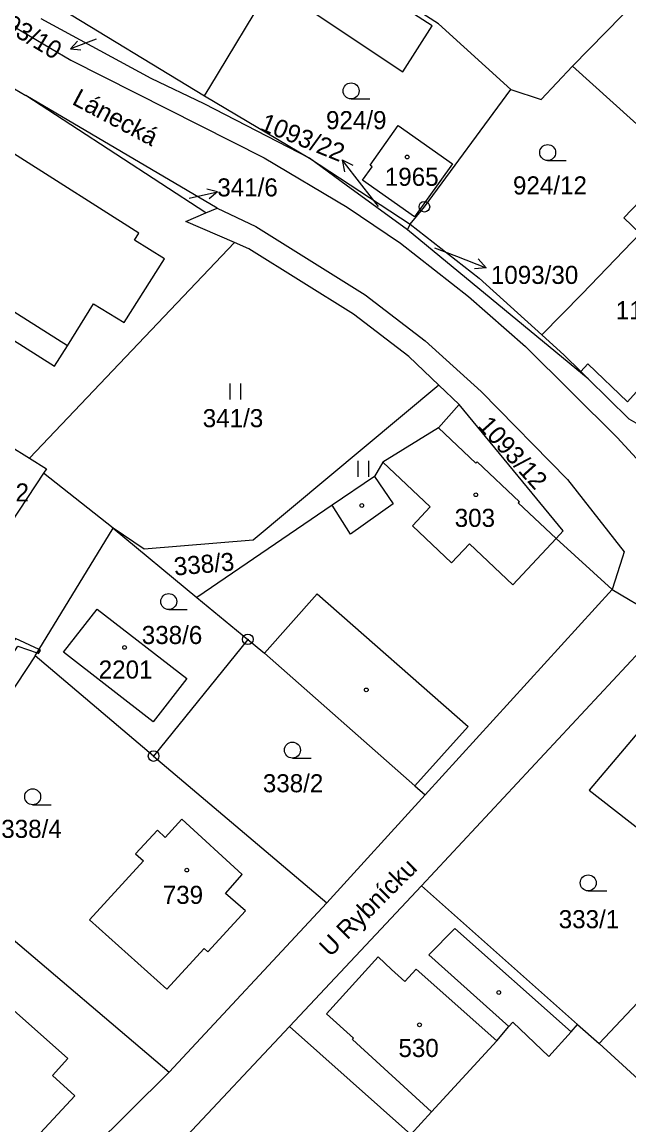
# Model space of a CAD drawing. Extents: x -680203 to -673936, y -1102717 to -1093650.
# Drawn here: x -679269.8 to -679212.8, y -1098015.1 to -1097911.3 of the extents above; entities that cross this region are included whole.
import ezdxf

# ---------------------------------------------------------------- set-up
doc = ezdxf.new("R2010")
doc.units = 0
for name, color, linetype in [('SOxx02xx_Koleje_param další_Popis10', 7, 'Continuous'), ('SOxx02xx_Staničení_Popis10', 7, 'Continuous'), ('SOxxxxxx_Koleje_hlavní_body_Popis10', 7, 'Continuous'), ('SOxxxxxx_Koleje_LN_parametry_Popis10', 7, 'Continuous'), ('SOxxxxxx_Koleje_param další_Popis10', 7, 'Continuous'), ('SOxxxxxx_Osa_bod_P', 7, 'Continuous'), ('SOxxxxxx_Staničení_Popis10', 7, 'Continuous'), ('x_prac', 7, 'Continuous')]:
    doc.layers.add(name, color=color, linetype=linetype)

msp = doc.modelspace()

# ---------------------------------------------------------------- linework, layer by layer
at = {"layer": 'SOxx02xx_Koleje_param další_Popis10'}
for centre, radius in [((-679231.98, -1097928.68), 0.5), ((-679231.98, -1097928.68), 0.0303), ((-679248.58, -1097969.38), 0.5), ((-679248.58, -1097969.38), 0.0303), ((-679257.44, -1097980.36), 0.5), ((-679257.44, -1097980.36), 0.0303)]:
    msp.add_circle(centre, radius, dxfattribs=at)
at = {"layer": 'SOxx02xx_Staničení_Popis10'}
for p, q in [((-679262.83, -1097912.9), (-679265.24, -1097913.82)), ((-679265.24, -1097913.82), (-679264.59, -1097913.11)), ((-679265.24, -1097913.82), (-679264.28, -1097913.92)), ((-679237.86, -1097926.65), (-679239.71, -1097924.28)), ((-679239.71, -1097924.28), (-679238.7, -1097924.77)), ((-679239.71, -1097924.28), (-679239.49, -1097925.38)), ((-679254.1, -1097927.88), (-679251.44, -1097927.27)), ((-679251.44, -1097927.27), (-679252.43, -1097927.03)), ((-679251.44, -1097927.27), (-679252.22, -1097927.92)), ((-679236.28, -1097928.65), (-679237.86, -1097926.65)), ((-679231.03, -1097932.54), (-679228.97, -1097933.34)), ((-679228.97, -1097933.34), (-679226.17, -1097934.42)), ((-679226.17, -1097934.42), (-679226.92, -1097933.59)), ((-679226.17, -1097934.42), (-679227.28, -1097934.52))]:
    msp.add_line(p, q, dxfattribs=at)
at = {"layer": 'SOxxxxxx_Koleje_hlavní_body_Popis10'}
for p, q in [((-679238.87, -1097918.53), (-679237.12, -1097918.53)), ((-679220.39, -1097924.33), (-679218.64, -1097924.33)), ((-679250.24, -1097946.81), (-679250.24, -1097945.31)), ((-679249.24, -1097946.81), (-679249.24, -1097945.31)), ((-679238.21, -1097954.09), (-679238.21, -1097952.59)), ((-679237.21, -1097954.09), (-679237.21, -1097952.59)), ((-679256.02, -1097966.58), (-679254.27, -1097966.58)), ((-679244.39, -1097980.55), (-679242.64, -1097980.55)), ((-679268.81, -1097984.94), (-679267.06, -1097984.94)), ((-679216.58, -1097993.05), (-679214.83, -1097993.05))]:
    msp.add_line(p, q, dxfattribs=at)
for centre in [(-679238.87, -1097917.78), (-679220.39, -1097923.58), (-679256.02, -1097965.83), (-679244.39, -1097979.8), (-679268.81, -1097984.19), (-679216.58, -1097992.3)]:
    msp.add_circle(centre, 0.75, dxfattribs=at)
at = {"layer": 'SOxxxxxx_Koleje_LN_parametry_Popis10'}
for points in [[(-679273.16, -1097973.42), (-679272.58, -1097973.72), (-679270.19, -1097970.03), (-679268.39, -1097970.65), (-679268.21, -1097970.35), (-679270.43, -1097969.29)], [(-679268.21, -1097970.35), (-679268.39, -1097970.65), (-679268.26, -1097970.7), (-679268.07, -1097970.42)]]:
    msp.add_lwpolyline(points, close=True, dxfattribs=at)
at = {"layer": 'SOxxxxxx_Koleje_param další_Popis10'}
for centre in [(-679233.59, -1097924), (-679227.15, -1097955.78), (-679237.87, -1097956.79), (-679260.17, -1097970.14), (-679237.44, -1097974.14), (-679254.32, -1097991.09), (-679224.99, -1098002.61), (-679232.44, -1098005.65)]:
    msp.add_circle(centre, 0.175, dxfattribs=at)
at = {"layer": 'SOxxxxxx_Staničení_Popis10'}
for p, q in [((-679265.53, -1097941.78), (-679283.18, -1097930.57)), ((-679230.66, -1097949.49), (-679227.14, -1097952.79)), ((-679231.43, -1097956.92), (-679235.89, -1097952.71)), ((-679227.14, -1097952.79), (-679227.03, -1097952.68)), ((-679227.03, -1097952.68), (-679223.04, -1097956.44)), ((-679236.67, -1097954.06), (-679234.9, -1097956.64)), ((-679234.9, -1097956.64), (-679238.93, -1097959.47)), ((-679223.04, -1097956.44), (-679223.15, -1097956.55)), ((-679223.15, -1097956.55), (-679219.6, -1097959.9)), ((-679238.93, -1097959.47), (-679240.65, -1097956.77)), ((-679233.1, -1097958.69), (-679231.43, -1097956.92)), ((-679229.42, -1097962.17), (-679233.1, -1097958.69)), ((-679227.75, -1097960.4), (-679229.42, -1097962.17)), ((-679223.68, -1097964.26), (-679227.75, -1097960.4)), ((-679219.6, -1097959.9), (-679223.68, -1097964.26)), ((-679247.02, -1097970.67), (-679242.05, -1097965.09)), ((-679242.05, -1097965.09), (-679227.85, -1097977.57)), ((-679227.85, -1097977.57), (-679232.87, -1097983.17)), ((-679231.55, -1097999.08), (-679229.12, -1097996.58)), ((-679229.12, -1097996.58), (-679218.19, -1098006.3)), ((-679241.18, -1098004.6), (-679236.33, -1097999.25)), ((-679236.33, -1097999.25), (-679235.06, -1098000.45)), ((-679224.04, -1098005.81), (-679231.55, -1097999.08)), ((-679235.06, -1098000.45), (-679233.81, -1098001.58)), ((-679233.81, -1098001.58), (-679232.75, -1098000.41)), ((-679232.75, -1098000.41), (-679225.17, -1098007.15)), ((-679238.63, -1098006.91), (-679241.18, -1098004.6)), ((-679238.75, -1098007.04), (-679238.63, -1098006.91)), ((-679231.31, -1098013.85), (-679238.75, -1098007.04))]:
    msp.add_line(p, q, dxfattribs=at)
at = {"layer": 'x_prac'}
for p, q in [((-679266.79, -1097909.64), (-679252.64, -1097918.24)), ((-679211.82, -1097909.04), (-679218.05, -1097915.45)), ((-679279.12, -1097912.51), (-679269.45, -1097918.21)), ((-679218.05, -1097915.45), (-679195.58, -1097935.81)), ((-679252.52, -1097929.25), (-679269.45, -1097918.21)), ((-679251.47, -1097928.8), (-679269.45, -1097918.21)), ((-679252.64, -1097918.24), (-679242.77, -1097924.11)), ((-679242.77, -1097924.11), (-679233.33, -1097930.32)), ((-679252.52, -1097929.25), (-679251.47, -1097928.8)), ((-679233.57, -1097930.84), (-679233.33, -1097930.32)), ((-679216.58, -1097944.86), (-679233.57, -1097930.84)), ((-679249.83, -1097932.05), (-679269.11, -1097952.33)), ((-679217.28, -1097944.17), (-679216.58, -1097944.86)), ((-679228.71, -1097947.3), (-679230.62, -1097945.47)), ((-679271.01, -1097951.15), (-679269.11, -1097952.33)), ((-679261.24, -1097958.92), (-679267.8, -1097953.75)), ((-679268.56, -1097970.93), (-679261.24, -1097958.92)), ((-679261.24, -1097958.92), (-679253.36, -1097965.43)), ((-679231.91, -1097984.02), (-679214.32, -1097964.7)), ((-679214.32, -1097964.7), (-679209.18, -1097967.77)), ((-679253.36, -1097965.43), (-679248.58, -1097969.38)), ((-679209.18, -1097967.77), (-679232.24, -1097992.58)), ((-679248.58, -1097969.38), (-679257.44, -1097980.36)), ((-679268.56, -1097970.93), (-679280.72, -1097989.05)), ((-679257.44, -1097980.36), (-679268.56, -1097970.93)), ((-679257.44, -1097980.36), (-679241.16, -1097994.18)), ((-679215.55, -1098007.41), (-679192.47, -1097982.8)), ((-679241.16, -1097994.18), (-679231.91, -1097984.02)), ((-679280.72, -1097989.05), (-679255.99, -1098010.09)), ((-679232.24, -1097992.58), (-679244.66, -1098005.8)), ((-679217.58, -1098005.61), (-679232.24, -1097992.58)), ((-679255.99, -1098010.09), (-679241.16, -1097994.18)), ((-679244.66, -1098005.8), (-679254.77, -1098016.61)), ((-679244.66, -1098005.8), (-679233.25, -1098015.97)), ((-679217.58, -1098005.61), (-679215.55, -1098007.41)), ((-679215.55, -1098007.41), (-679199.39, -1098022.22)), ((-679272.43, -1098026.46), (-679255.99, -1098010.09))]:
    msp.add_line(p, q, dxfattribs=at)
for points in [[(-679433.1, -1097805.8), (-679408.01, -1097822.16), (-679393.41, -1097831.27), (-679382.99, -1097837.58), (-679348.75, -1097857.3), (-679337.29, -1097864.26), (-679320.46, -1097875.6), (-679311.54, -1097882.15), (-679283.96, -1097902.87), (-679274.82, -1097909.22), (-679265.22, -1097914.88), (-679247.05, -1097924.07), (-679239.24, -1097928.72), (-679234.23, -1097932.11), (-679227.84, -1097937.13), (-679222.47, -1097941.84), (-679213.85, -1097950.4), (-679211.7, -1097952.73)], [(-679252.64, -1097918.24), (-679252.15, -1097917.43), (-679246.34, -1097907.8), (-679243.95, -1097909.38), (-679234.01, -1097915.97), (-679231.25, -1097911.67), (-679241.19, -1097905.22), (-679243.77, -1097903.54), (-679243.55, -1097903.18)], [(-679223.85, -1097917.65), (-679230.66, -1097911.47), (-679243.55, -1097903.18)], [(-679242.77, -1097924.11), (-679252.7, -1097919.01), (-679257.68, -1097916.6), (-679268.01, -1097911.01)], [(-679223.85, -1097917.65), (-679220.99, -1097918.59), (-679218.05, -1097915.45)], [(-679289.52, -1097926.55), (-679283.18, -1097930.57), (-679284.88, -1097933.25), (-679278.23, -1097937.47), (-679277.75, -1097936.71), (-679266.75, -1097943.69), (-679265.53, -1097941.78), (-679263.08, -1097937.81), (-679260.22, -1097939.57), (-679256.41, -1097933.59), (-679259.25, -1097931.81), (-679258.84, -1097931.17), (-679281.74, -1097916.6)], [(-679233.33, -1097930.32), (-679231.98, -1097928.68), (-679223.85, -1097917.65)], [(-679232.9, -1097929.62), (-679237.8, -1097926.18), (-679236.9, -1097924.92), (-679237.09, -1097924.76), (-679234.43, -1097921.04), (-679229.34, -1097924.65), (-679232.9, -1097929.62)], [(-679233.57, -1097930.84), (-679239.34, -1097926.64), (-679242.77, -1097924.11)], [(-679217.28, -1097944.17), (-679216.61, -1097943.47), (-679212.88, -1097947.04), (-679209.85, -1097943.64), (-679201.66, -1097934.99), (-679210.16, -1097926.53), (-679213.23, -1097929.72), (-679211.69, -1097931.19), (-679217.15, -1097936.86), (-679220.95, -1097940.72)], [(-679249.83, -1097932.05), (-679254.41, -1097930.07), (-679252.52, -1097929.25)], [(-679251.47, -1097928.8), (-679247.83, -1097930.55), (-679237.55, -1097936.96), (-679231.9, -1097941.28), (-679226.63, -1097946.05), (-679218.51, -1097954.35), (-679213.19, -1097961.14), (-679213.36, -1097961.66), (-679214.32, -1097964.7)], [(-679233.33, -1097930.32), (-679226.82, -1097935.39), (-679220.95, -1097940.72)], [(-679230.62, -1097945.47), (-679233.43, -1097942.77), (-679238.66, -1097938.8), (-679248.49, -1097932.63), (-679249.83, -1097932.05)], [(-679220.95, -1097940.72), (-679218.85, -1097942.63), (-679217.28, -1097944.17)], [(-679216.58, -1097944.86), (-679212.76, -1097948.63), (-679210.34, -1097950.02), (-679209.21, -1097950)], [(-679230.62, -1097945.47), (-679248.09, -1097960.05), (-679258.34, -1097960.89), (-679261.24, -1097958.92)], [(-679228.71, -1097947.3), (-679230.66, -1097949.49), (-679235.89, -1097952.71), (-679236.67, -1097954.06), (-679240.65, -1097956.77), (-679253.36, -1097965.43)], [(-679214.32, -1097964.7), (-679219.6, -1097959.9), (-679218.92, -1097959.17), (-679228.71, -1097947.3)], [(-679269.11, -1097952.33), (-679267.52, -1097953.33), (-679267.8, -1097953.75)], [(-679267.8, -1097953.75), (-679270.85, -1097958.42), (-679275.19, -1097955.69)], [(-679257.47, -1097977.15), (-679265.9, -1097970.6), (-679262.74, -1097966.53), (-679254.31, -1097973.08), (-679257.47, -1097977.15)], [(-679248.58, -1097969.38), (-679247.02, -1097970.67), (-679232.87, -1097983.17), (-679231.91, -1097984.02)], [(-679202.77, -1097979.79), (-679207.48, -1097975.92), (-679208.74, -1097977.44), (-679210.24, -1097976.2), (-679216.48, -1097983.58), (-679209.07, -1097989.38), (-679203.16, -1097982.08), (-679204.05, -1097981.33), (-679202.77, -1097979.79)], [(-679249.12, -1097991.51), (-679254.77, -1097986.3), (-679256.34, -1097988.01), (-679257.08, -1097987.32), (-679259.13, -1097989.55), (-679258.39, -1097990.23), (-679263.48, -1097995.77), (-679256.19, -1098002.3), (-679252.68, -1097998.47), (-679252.35, -1097998.78), (-679248.81, -1097994.91), (-679250.67, -1097993.28), (-679249.12, -1097991.51)], [(-679279.06, -1098012.82), (-679271.71, -1098019.72), (-679264.84, -1098012.33), (-679266.95, -1098010.43), (-679265.51, -1098008.83), (-679270.88, -1098004.01), (-679279.06, -1098012.82)], [(-679233.25, -1098015.97), (-679231.31, -1098013.85), (-679225.17, -1098007.15), (-679224.04, -1098005.81), (-679223.68, -1098005.41), (-679220.27, -1098008.63), (-679218.19, -1098006.3), (-679217.58, -1098005.61)]]:
    msp.add_lwpolyline(points, dxfattribs=at)

# ---------------------------------------------------------------- texts
at = {"layer": 'SOxx02xx_Staničení_Popis10'}
for s, rotation, p in [('Lánecká', 332, (-679265.2, -1097918.99)), ('U Rybnícku', 45, (-679240.84, -1097999.34))]:
    msp.add_text(s, height=1.7, rotation=rotation, dxfattribs=at).set_placement(p)
at = {"layer": 'SOxxxxxx_Osa_bod_P'}
for s, rotation, p in [('1093/10', 329, (-679273.79, -1097910.66)), ('1093/22', 338, (-679247.54, -1097921.41)), ('1093/12', 312, (-679227.04, -1097949.33)), ('338/3', 5, (-679255.46, -1097963.39))]:
    msp.add_text(s, height=1.7, rotation=rotation, dxfattribs=at).set_placement(p)
for s, p in [('924/9', (-679241.23, -1097921.38)), ('1965', (-679235.7, -1097926.71)), ('341/6', (-679251.45, -1097927.71)), ('924/12', (-679223.65, -1097927.52)), ('1093/30', (-679225.73, -1097935.94)), ('1158', (-679213.99, -1097939.26)), ('341/3', (-679252.82, -1097949.42)), ('2092', (-679274.21, -1097956.41)), ('303', (-679229.13, -1097958.8)), ('338/6', (-679258.55, -1097969.82)), ('2201', (-679262.6, -1097973.07)), ('338/2', (-679247.17, -1097983.77)), ('338/4', (-679271.76, -1097988.06)), ('739', (-679256.58, -1097994.27)), ('333/1', (-679219.35, -1097996.56)), ('530', (-679234.42, -1098008.68))]:
    msp.add_text(s, height=1.7, dxfattribs=at).set_placement(p)

doc.saveas('drawing.dxf')
